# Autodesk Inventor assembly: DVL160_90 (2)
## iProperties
Created: 2009-09
Part Number: DVL160_90 (2)
Document SubType Name: Assembly
Designer: TB
Mass: 9007.16 g
Surface Area: 8387.75 cm^2
Volume: 9007.16 cm^3
Density: 1 g/cm^3
Description: KM DVL 160/90 - 100 mm
Slaglengde: 100.000 mm
Author: TB
